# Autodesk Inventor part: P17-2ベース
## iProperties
Created: 2008-07
Part Number: P17-2ベース
Document SubType Name: Modeling
Designer: y-shimohigashi
Density: 1 g/cm^3
Stock Number: P17-2ベース
Author: y-shimohigashi
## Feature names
1. 押し出し1 [Extrusion]
2. 押し出し2 [Extrusion]
3. 押し出し3 [Extrusion]
4. 押し出し4 [Extrusion]
5. 穴1 [Hole]
6. 押し出し5 [Extrusion]
7. 穴2 [Hole]
8. 放射状パターン1 [Circular Pattern]
9. 穴3 [Hole]
10. フィレット1 [Fillet]
11. フィレット2 [Fillet]
12. フィレット3 [Fillet]
13. 面取り1 [Chamfer]
